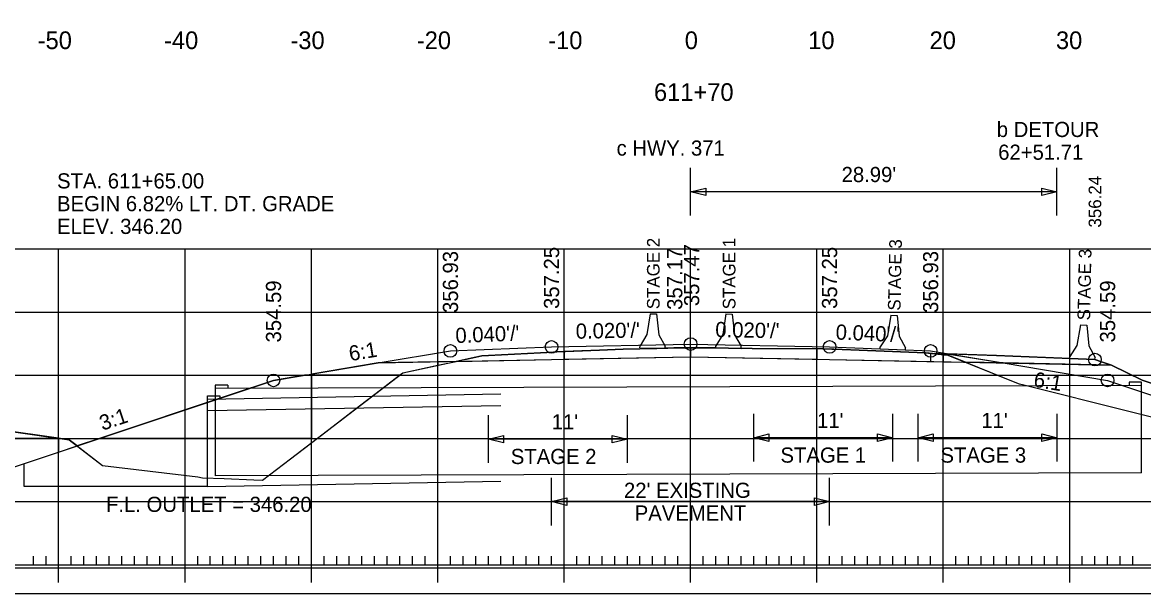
# Model space of a CAD drawing. Extents: x 1368910 to 1369601, y 380116 to 380950.
# Drawn here: x 1369384.7 to 1369473.4, y 380417.2 to 380462.3 of the extents above; entities that cross this region are included whole.
import ezdxf

# ---------------------------------------------------------------- set-up
doc = ezdxf.new("R2010")
doc.units = 0
for name, color, linetype in [('_STAGE 1 CUT', 7, 'Continuous'), ('_STAGE 1 FILL', 7, 'Continuous'), ('_STAGE 2 CUT', 7, 'Continuous'), ('_STAGE 2 FILL', 7, 'Continuous'), ('_STAGE 4 CUT', 7, 'Continuous'), ('Notes', 7, 'Continuous'), ('R_Alt Surface', 7, 'Continuous'), ('R_Axis', 7, 'Continuous'), ('R_Axis Annot', 7, 'Continuous'), ('R_Border Plan-Plan', 7, 'Continuous'), ('R_CONC BARRIER', 7, 'Continuous'), ('R_Detour', 7, 'Continuous'), ('R_Detour Surface', 7, 'Continuous'), ('R_Exist Surface', 7, 'Continuous'), ('R_Fin Surface', 7, 'Continuous'), ('R_Grid', 7, 'Continuous'), ('R_No Plot', 7, 'Continuous'), ('R_ROW Annot', 7, 'Continuous'), ('R_Water', 7, 'Continuous'), ('R_Xsect Elev', 7, 'Continuous'), ('R_Xsect Elev Detour', 7, 'Continuous'), ('R_Xsect Slope', 7, 'Continuous')]:
    doc.layers.add(name, color=color, linetype=linetype)

msp = doc.modelspace()

# ---------------------------------------------------------------- linework, layer by layer
at = {"layer": '_STAGE 1 CUT'}
for p, q in [((1369437.59, 380435.886), (1369437.59, 380436.594)), ((1369419.052, 380435.516), (1369426.59, 380435.666)), ((1369426.59, 380435.666), (1369427.59, 380435.686)), ((1369427.59, 380435.686), (1369427.59, 380436.292)), ((1369427.59, 380436.292), (1369427.59, 380435.686)), ((1369427.59, 380435.686), (1369437.59, 380435.886)), ((1369387.59, 380429.441), (1369378.835, 380430.689)), ((1369387.59, 380429.421), (1369377.59, 380429.421)), ((1369377.59, 380429.421), (1369387.59, 380429.421)), ((1369387.59, 380429.421), (1369387.59, 380429.441)), ((1369387.59, 380428.346), (1369387.59, 380429.421)), ((1369387.732, 380429.421), (1369387.59, 380429.421)), ((1369387.59, 380429.421), (1369387.59, 380428.346)), ((1369387.59, 380428.346), (1369389.057, 380428.836)), ((1369379.419, 380425.623), (1369387.59, 380428.346))]:
    msp.add_line(p, q, dxfattribs=at)
for points in [[(1369437.59, 380436.594), (1369437.463, 380436.593), (1369437.33, 380436.595), (1369436.264, 380436.589), (1369435.797, 380436.559), (1369435.59, 380436.553), (1369434.929, 380436.533), (1369432.263, 380436.481), (1369430.399, 380436.402), (1369427.59, 380436.292)], [(1369427.59, 380436.292), (1369427.004, 380436.269), (1369426.753, 380436.249), (1369421.601, 380435.996), (1369421.087, 380435.969), (1369420.613, 380435.845), (1369419.052, 380435.516)], [(1369389.057, 380428.836), (1369388.429, 380429.321), (1369387.732, 380429.421)]]:
    msp.add_lwpolyline(points, dxfattribs=at)
at = {"layer": '_STAGE 1 FILL'}
for p, q in [((1369417.59, 380435.208), (1369419.052, 380435.516)), ((1369419.052, 380435.516), (1369417.59, 380435.486)), ((1369412.863, 380435.392), (1369407.59, 380434.513)), ((1369417.59, 380435.486), (1369412.863, 380435.392)), ((1369417.59, 380435.486), (1369417.59, 380435.208)), ((1369417.59, 380435.208), (1369417.59, 380435.486)), ((1369407.036, 380434.421), (1369404.59, 380434.013)), ((1369407.59, 380434.421), (1369407.036, 380434.421)), ((1369407.59, 380434.513), (1369407.59, 380434.421)), ((1369407.59, 380434.421), (1369414.554, 380434.421)), ((1369414.554, 380434.421), (1369407.59, 380434.421)), ((1369407.59, 380434.421), (1369407.59, 380432.947)), ((1369407.59, 380432.947), (1369407.59, 380434.421)), ((1369390.813, 380429.421), (1369389.057, 380428.836)), ((1369390.813, 380429.421), (1369407.59, 380429.421)), ((1369407.59, 380429.421), (1369390.813, 380429.421)), ((1369407.59, 380429.421), (1369408.032, 380429.421)), ((1369407.59, 380429.082), (1369407.59, 380429.421))]:
    msp.add_line(p, q, dxfattribs=at)
for points in [[(1369414.554, 380434.421), (1369414.819, 380434.624), (1369417.59, 380435.208)], [(1369404.59, 380434.013), (1369401.171, 380432.873), (1369390.813, 380429.421)], [(1369408.032, 380429.421), (1369411.384, 380431.991), (1369412.708, 380433.006), (1369414.554, 380434.421)], [(1369407.59, 380432.947), (1369407.59, 380431.947), (1369407.59, 380429.421)], [(1369407.59, 380429.421), (1369407.59, 380431.947), (1369407.59, 380432.947)], [(1369389.057, 380428.836), (1369391.051, 380427.292), (1369398.609, 380426.388), (1369398.964, 380426.295), (1369400.673, 380426.251), (1369403.029, 380426.16), (1369403.724, 380426.13), (1369405.923, 380427.804), (1369407.59, 380429.082)]]:
    msp.add_lwpolyline(points, dxfattribs=at)
at = {"layer": '_STAGE 2 CUT'}
for p, q in [((1369437.59, 380436.594), (1369437.59, 380435.886)), ((1369441.59, 380436.548), (1369439.59, 380436.588)), ((1369441.59, 380436.556), (1369441.59, 380436.548)), ((1369447.59, 380436.519), (1369447.59, 380435.686)), ((1369447.59, 380435.686), (1369447.59, 380436.519)), ((1369437.59, 380435.886), (1369447.59, 380435.686)), ((1369447.59, 380435.686), (1369448.59, 380435.666)), ((1369448.59, 380435.666), (1369457.59, 380435.486)), ((1369457.59, 380435.486), (1369457.59, 380436.053)), ((1369457.59, 380436.053), (1369457.59, 380435.486)), ((1369457.59, 380435.486), (1369459.349, 380435.451))]:
    msp.add_line(p, q, dxfattribs=at)
for points in [[(1369439.59, 380436.588), (1369438.794, 380436.601), (1369437.59, 380436.594)], [(1369447.59, 380436.519), (1369442.479, 380436.542), (1369441.59, 380436.556)], [(1369457.59, 380436.053), (1369456.193, 380436.192), (1369451.59, 380436.381), (1369448.928, 380436.485), (1369448.773, 380436.49), (1369448.065, 380436.517), (1369447.59, 380436.519)], [(1369459.349, 380435.451), (1369457.951, 380436.013), (1369457.653, 380436.046), (1369457.59, 380436.053)]]:
    msp.add_lwpolyline(points, dxfattribs=at)
at = {"layer": '_STAGE 2 FILL'}
for p, q in [((1369462.317, 380435.392), (1369459.349, 380435.451)), ((1369470.909, 380435.22), (1369462.317, 380435.392))]:
    msp.add_line(p, q, dxfattribs=at)
for points in [[(1369459.349, 380435.451), (1369463.243, 380433.885), (1369463.583, 380433.733), (1369463.856, 380433.68), (1369481.105, 380429.375), (1369481.631, 380429.201), (1369481.702, 380429.203), (1369484.652, 380429.137), (1369485.064, 380429.188), (1369486.052, 380429.311)], [(1369462.317, 380435.392), (1369462.317, 380435.392)], [(1369487.523, 380429.468), (1369485.977, 380429.824), (1369473.317, 380434.045), (1369470.909, 380435.22)]]:
    msp.add_lwpolyline(points, dxfattribs=at)
at = {"layer": '_STAGE 4 CUT'}
for p, q in [((1369457.904, 380436.127), (1369462.315, 380435.392)), ((1369462.315, 380435.392), (1369462.317, 380435.392))]:
    msp.add_line(p, q, dxfattribs=at)
for points in [[(1369470.118, 380435.484), (1369469.59, 380435.66), (1369467.592, 380435.74), (1369461.79, 380435.972), (1369457.904, 380436.127)], [(1369462.317, 380435.392), (1369462.317, 380435.392)], [(1369462.317, 380435.392), (1369470.59, 380434.013), (1369485.064, 380429.188), (1369485.665, 380428.988), (1369489.605, 380428.988)], [(1369489.605, 380428.988), (1369487.523, 380429.468), (1369485.977, 380429.824), (1369473.317, 380434.045), (1369470.909, 380435.22), (1369470.118, 380435.484)]]:
    msp.add_lwpolyline(points, dxfattribs=at)
at = {"layer": 'R_Alt Surface'}
for points in [[(1369412.863, 380435.392), (1369426.59, 380435.666), (1369437.59, 380435.886), (1369448.59, 380435.666), (1369462.317, 380435.392)], [(1369456.59, 380436.18), (1369456.59, 380435.507), (1369470.909, 380435.22)]]:
    msp.add_lwpolyline(points, dxfattribs=at)
at = {"layer": 'R_Axis'}
for p, q in [((1369387.59, 380418.021), (1369387.59, 380420.821)), ((1369397.59, 380418.021), (1369397.59, 380420.821)), ((1369407.59, 380418.021), (1369407.59, 380420.821)), ((1369417.59, 380418.021), (1369417.59, 380420.821)), ((1369427.59, 380418.021), (1369427.59, 380420.821)), ((1369437.59, 380418.021), (1369437.59, 380420.821)), ((1369447.59, 380418.021), (1369447.59, 380420.821)), ((1369457.59, 380418.021), (1369457.59, 380420.821)), ((1369467.59, 380418.021), (1369467.59, 380420.821)), ((1369385.59, 380419.421), (1369385.59, 380420.121)), ((1369386.59, 380419.421), (1369386.59, 380420.121)), ((1369388.59, 380419.421), (1369388.59, 380420.121)), ((1369389.59, 380419.421), (1369389.59, 380420.121)), ((1369390.59, 380419.421), (1369390.59, 380420.121)), ((1369391.59, 380419.421), (1369391.59, 380420.121)), ((1369392.59, 380419.421), (1369392.59, 380420.121)), ((1369393.59, 380419.421), (1369393.59, 380420.121)), ((1369394.59, 380419.421), (1369394.59, 380420.121)), ((1369395.59, 380419.421), (1369395.59, 380420.121)), ((1369396.59, 380419.421), (1369396.59, 380420.121)), ((1369398.59, 380419.421), (1369398.59, 380420.121)), ((1369399.59, 380419.421), (1369399.59, 380420.121)), ((1369400.59, 380419.421), (1369400.59, 380420.121)), ((1369401.59, 380419.421), (1369401.59, 380420.121)), ((1369402.59, 380419.421), (1369402.59, 380420.121)), ((1369403.59, 380419.421), (1369403.59, 380420.121)), ((1369404.59, 380419.421), (1369404.59, 380420.121)), ((1369405.59, 380419.421), (1369405.59, 380420.121)), ((1369406.59, 380419.421), (1369406.59, 380420.121)), ((1369408.59, 380419.421), (1369408.59, 380420.121)), ((1369409.59, 380419.421), (1369409.59, 380420.121)), ((1369410.59, 380419.421), (1369410.59, 380420.121)), ((1369411.59, 380419.421), (1369411.59, 380420.121)), ((1369412.59, 380419.421), (1369412.59, 380420.121)), ((1369413.59, 380419.421), (1369413.59, 380420.121)), ((1369414.59, 380419.421), (1369414.59, 380420.121)), ((1369415.59, 380419.421), (1369415.59, 380420.121)), ((1369416.59, 380419.421), (1369416.59, 380420.121)), ((1369418.59, 380419.421), (1369418.59, 380420.121)), ((1369419.59, 380419.421), (1369419.59, 380420.121)), ((1369420.59, 380419.421), (1369420.59, 380420.121)), ((1369421.59, 380419.421), (1369421.59, 380420.121)), ((1369422.59, 380419.421), (1369422.59, 380420.121)), ((1369423.59, 380419.421), (1369423.59, 380420.121)), ((1369424.59, 380419.421), (1369424.59, 380420.121)), ((1369425.59, 380419.421), (1369425.59, 380420.121)), ((1369426.59, 380419.421), (1369426.59, 380420.121)), ((1369428.59, 380419.421), (1369428.59, 380420.121)), ((1369429.59, 380419.421), (1369429.59, 380420.121)), ((1369430.59, 380419.421), (1369430.59, 380420.121)), ((1369431.59, 380419.421), (1369431.59, 380420.121)), ((1369432.59, 380419.421), (1369432.59, 380420.121)), ((1369433.59, 380419.421), (1369433.59, 380420.121)), ((1369434.59, 380419.421), (1369434.59, 380420.121)), ((1369435.59, 380419.421), (1369435.59, 380420.121)), ((1369436.59, 380419.421), (1369436.59, 380420.121)), ((1369438.59, 380419.421), (1369438.59, 380420.121)), ((1369439.59, 380419.421), (1369439.59, 380420.121)), ((1369440.59, 380419.421), (1369440.59, 380420.121)), ((1369441.59, 380419.421), (1369441.59, 380420.121)), ((1369442.59, 380419.421), (1369442.59, 380420.121)), ((1369443.59, 380419.421), (1369443.59, 380420.121)), ((1369444.59, 380419.421), (1369444.59, 380420.121)), ((1369445.59, 380419.421), (1369445.59, 380420.121)), ((1369446.59, 380419.421), (1369446.59, 380420.121)), ((1369448.59, 380419.421), (1369448.59, 380420.121)), ((1369449.59, 380419.421), (1369449.59, 380420.121)), ((1369450.59, 380419.421), (1369450.59, 380420.121)), ((1369451.59, 380419.421), (1369451.59, 380420.121)), ((1369452.59, 380419.421), (1369452.59, 380420.121)), ((1369453.59, 380419.421), (1369453.59, 380420.121)), ((1369454.59, 380419.421), (1369454.59, 380420.121)), ((1369455.59, 380419.421), (1369455.59, 380420.121)), ((1369456.59, 380419.421), (1369456.59, 380420.121)), ((1369458.59, 380419.421), (1369458.59, 380420.121)), ((1369459.59, 380419.421), (1369459.59, 380420.121)), ((1369460.59, 380419.421), (1369460.59, 380420.121)), ((1369461.59, 380419.421), (1369461.59, 380420.121)), ((1369462.59, 380419.421), (1369462.59, 380420.121)), ((1369463.59, 380419.421), (1369463.59, 380420.121)), ((1369464.59, 380419.421), (1369464.59, 380420.121)), ((1369465.59, 380419.421), (1369465.59, 380420.121)), ((1369466.59, 380419.421), (1369466.59, 380420.121)), ((1369468.59, 380419.421), (1369468.59, 380420.121)), ((1369469.59, 380419.421), (1369469.59, 380420.121)), ((1369470.59, 380419.421), (1369470.59, 380420.121)), ((1369471.59, 380419.421), (1369471.59, 380420.121)), ((1369472.59, 380419.421), (1369472.59, 380420.121)), ((1369297.59, 380419.421), (1369577.59, 380419.421))]:
    msp.add_line(p, q, dxfattribs=at)
at = {"layer": 'R_Border Plan-Plan'}
msp.add_line((1369279.59, 380417.151), (1369595.77, 380417.151), dxfattribs=at)
at = {"layer": 'R_CONC BARRIER'}
for p, q in [((1369434.394, 380439.277), (1369434.894, 380439.267)), ((1369440.394, 380439.272), (1369440.894, 380439.262)), ((1369453.447, 380439.175), (1369453.947, 380439.155)), ((1369468.449, 380438.408), (1369468.948, 380438.388)), ((1369433.59, 380436.593), (1369433.594, 380436.759)), ((1369433.59, 380436.593), (1369435.59, 380436.553)), ((1369435.59, 380436.553), (1369435.593, 380436.719)), ((1369439.59, 380436.588), (1369439.593, 380436.755)), ((1369439.59, 380436.588), (1369441.59, 380436.548)), ((1369441.59, 380436.548), (1369441.593, 380436.715)), ((1369452.59, 380436.507), (1369452.597, 380436.673)), ((1369452.59, 380436.507), (1369454.588, 380436.427)), ((1369454.588, 380436.427), (1369454.595, 380436.593)), ((1369467.592, 380435.74), (1369467.598, 380435.907)), ((1369467.592, 380435.74), (1369469.59, 380435.66)), ((1369469.59, 380435.66), (1369469.597, 380435.827))]:
    msp.add_line(p, q, dxfattribs=at)
for points in [[(1369434.394, 380439.277), (1369434.143, 380437.639), (1369433.594, 380436.759)], [(1369434.894, 380439.267), (1369435.08, 380437.62), (1369435.593, 380436.719)], [(1369440.394, 380439.272), (1369440.142, 380437.634), (1369439.593, 380436.755)], [(1369440.894, 380439.262), (1369441.079, 380437.616), (1369441.593, 380436.715)], [(1369453.447, 380439.175), (1369453.163, 380437.542), (1369452.597, 380436.673)], [(1369453.947, 380439.155), (1369454.1, 380437.504), (1369454.595, 380436.593)], [(1369468.449, 380438.408), (1369468.165, 380436.775), (1369467.598, 380435.907)], [(1369468.948, 380438.388), (1369469.101, 380436.738), (1369469.597, 380435.827)]]:
    msp.add_lwpolyline(points, dxfattribs=at)
at = {"layer": 'R_Detour'}
for p, q in [((1369473.286, 380433.866), (1369472.286, 380433.866)), ((1369472.286, 380433.866), (1369472.286, 380433.613)), ((1369473.286, 380433.616), (1369473.286, 380433.866)), ((1369400.983, 380433.631), (1369399.983, 380433.631)), ((1369399.983, 380433.631), (1369399.983, 380433.378)), ((1369473.286, 380433.616), (1369399.983, 380433.378)), ((1369399.983, 380433.378), (1369399.983, 380426.461)), ((1369400.983, 380433.631), (1369400.983, 380433.378)), ((1369473.286, 380432.699), (1369473.286, 380433.616)), ((1369473.286, 380426.699), (1369473.286, 380432.699)), ((1369473.286, 380426.699), (1369399.983, 380426.461))]:
    msp.add_line(p, q, dxfattribs=at)
at = {"layer": 'R_Detour Surface'}
msp.add_lwpolyline([(1369456.59, 380436.18), (1369461.79, 380435.972), (1369469.59, 380435.66), (1369470.118, 380435.484), (1369470.909, 380435.22), (1369473.317, 380434.045), (1369485.977, 380429.824), (1369489.605, 380428.988)], dxfattribs=at)
at = {"layer": 'R_Exist Surface'}
msp.add_lwpolyline([(1369378.835, 380430.689), (1369388.429, 380429.321), (1369391.051, 380427.292), (1369398.609, 380426.388), (1369398.964, 380426.295), (1369400.673, 380426.251), (1369403.029, 380426.16), (1369403.724, 380426.13), (1369405.923, 380427.804), (1369414.819, 380434.624), (1369420.613, 380435.845), (1369421.087, 380435.969), (1369421.601, 380435.996), (1369426.753, 380436.249), (1369427.004, 380436.269), (1369430.399, 380436.402), (1369432.263, 380436.481), (1369434.929, 380436.533), (1369435.797, 380436.559), (1369436.264, 380436.589), (1369437.33, 380436.595), (1369437.463, 380436.593), (1369438.794, 380436.601), (1369442.479, 380436.542), (1369448.065, 380436.517), (1369448.773, 380436.49), (1369448.928, 380436.485), (1369451.59, 380436.381), (1369456.193, 380436.192), (1369457.653, 380436.046), (1369457.951, 380436.013), (1369463.243, 380433.885), (1369463.583, 380433.733), (1369463.856, 380433.68), (1369481.105, 380429.375)], dxfattribs=at)
at = {"layer": 'R_Fin Surface'}
msp.add_lwpolyline([(1369354.292, 380430.661), (1369369.413, 380425.621), (1369379.413, 380425.621), (1369404.59, 380434.013), (1369412.863, 380435.392), (1369418.59, 380436.346), (1369426.59, 380436.666), (1369437.59, 380436.886), (1369448.59, 380436.666), (1369456.59, 380436.346), (1369462.317, 380435.392), (1369470.59, 380434.013), (1369485.665, 380428.988), (1369490.579, 380428.988), (1369494.234, 380430.207)], dxfattribs=at)
at = {"layer": 'R_Grid'}
for p, q in [((1369297.59, 380444.421), (1369577.59, 380444.421)), ((1369297.59, 380444.421), (1369577.59, 380444.421)), ((1369387.59, 380419.421), (1369387.59, 380444.421)), ((1369387.59, 380419.421), (1369387.59, 380444.421)), ((1369397.59, 380419.421), (1369397.59, 380444.421)), ((1369397.59, 380419.421), (1369397.59, 380444.421)), ((1369407.59, 380419.421), (1369407.59, 380444.421)), ((1369407.59, 380419.421), (1369407.59, 380444.421)), ((1369417.59, 380419.421), (1369417.59, 380444.421)), ((1369417.59, 380419.421), (1369417.59, 380444.421)), ((1369427.59, 380419.421), (1369427.59, 380444.421)), ((1369427.59, 380419.421), (1369427.59, 380444.421)), ((1369437.59, 380419.421), (1369437.59, 380444.421)), ((1369437.59, 380419.421), (1369437.59, 380444.421)), ((1369447.59, 380419.421), (1369447.59, 380444.421)), ((1369447.59, 380419.421), (1369447.59, 380444.421)), ((1369457.59, 380419.421), (1369457.59, 380444.421)), ((1369457.59, 380419.421), (1369457.59, 380444.421)), ((1369467.59, 380419.421), (1369467.59, 380444.421)), ((1369467.59, 380419.421), (1369467.59, 380444.421)), ((1369297.59, 380439.421), (1369577.59, 380439.421)), ((1369297.59, 380439.421), (1369577.59, 380439.421)), ((1369297.59, 380434.421), (1369577.59, 380434.421)), ((1369297.59, 380434.421), (1369577.59, 380434.421)), ((1369297.59, 380429.421), (1369577.59, 380429.421)), ((1369297.59, 380429.421), (1369577.59, 380429.421)), ((1369297.59, 380424.421), (1369577.59, 380424.421)), ((1369297.59, 380424.421), (1369577.59, 380424.421)), ((1369297.59, 380419.421), (1369577.59, 380419.421)), ((1369297.59, 380419.421), (1369577.59, 380419.421))]:
    msp.add_line(p, q, dxfattribs=at)
at = {"layer": 'R_No Plot'}
msp.add_lwpolyline([(1369593.77, 380419.151), (1369281.59, 380419.151), (1369281.59, 380517.881), (1369531.13, 380517.881), (1369531.13, 380508.001), (1369548.67, 380508.001), (1369572.77, 380508.001), (1369572.77, 380485.668), (1369593.77, 380485.668)], close=True, dxfattribs=at)
for centre in [(1369437.59, 380436.886), (1369418.59, 380436.346), (1369426.59, 380436.666), (1369448.59, 380436.666), (1369456.59, 380436.346), (1369469.59, 380435.66), (1369404.59, 380434.013), (1369470.59, 380434.013)]:
    msp.add_circle(centre, 0.5, dxfattribs=at)
at = {"layer": 'R_ROW Annot'}
for p, q in [((1369437.59, 380447.047), (1369437.59, 380450.816)), ((1369466.58, 380447.047), (1369466.58, 380450.816)), ((1369466.58, 380448.932), (1369437.59, 380448.932)), ((1369421.59, 380427.482), (1369421.59, 380431.251)), ((1369432.59, 380427.482), (1369432.59, 380431.251)), ((1369442.59, 380427.592), (1369442.59, 380431.36)), ((1369453.59, 380427.592), (1369453.59, 380431.36)), ((1369455.59, 380427.592), (1369455.59, 380431.36)), ((1369466.59, 380427.592), (1369466.59, 380431.36)), ((1369432.59, 380429.366), (1369421.59, 380429.366)), ((1369453.59, 380429.476), (1369442.59, 380429.476)), ((1369466.59, 380429.476), (1369455.59, 380429.476)), ((1369426.59, 380422.537), (1369426.59, 380426.305)), ((1369448.59, 380422.537), (1369448.59, 380426.305)), ((1369448.59, 380424.421), (1369426.59, 380424.421))]:
    msp.add_line(p, q, dxfattribs=at)
for points in [[(1369438.79, 380448.632), (1369437.59, 380448.932), (1369438.79, 380449.232)], [(1369465.38, 380449.232), (1369466.58, 380448.932), (1369465.38, 380448.632)], [(1369422.79, 380429.066), (1369421.59, 380429.366), (1369422.79, 380429.666)], [(1369431.39, 380429.666), (1369432.59, 380429.366), (1369431.39, 380429.066)], [(1369443.79, 380429.176), (1369442.59, 380429.476), (1369443.79, 380429.776)], [(1369452.39, 380429.776), (1369453.59, 380429.476), (1369452.39, 380429.176)], [(1369456.79, 380429.176), (1369455.59, 380429.476), (1369456.79, 380429.776)], [(1369465.39, 380429.776), (1369466.59, 380429.476), (1369465.39, 380429.176)], [(1369427.79, 380424.121), (1369426.59, 380424.421), (1369427.79, 380424.721)], [(1369447.39, 380424.721), (1369448.59, 380424.421), (1369447.39, 380424.121)]]:
    msp.add_lwpolyline(points, close=True, dxfattribs=at)
at = {"layer": 'R_Water'}
for p, q in [((1369399.355, 380432.537), (1369422.59, 380432.948)), ((1369399.355, 380431.621), (1369422.59, 380432.031)), ((1369399.355, 380425.621), (1369422.59, 380426.031))]:
    msp.add_line(p, q, dxfattribs=at)
for points in [[(1369399.355, 380425.621), (1369399.355, 380431.621), (1369399.355, 380432.537), (1369399.355, 380432.787), (1369400.355, 380432.787), (1369400.355, 380432.537)], [(1369399.355, 380425.621), (1369384.855, 380425.621), (1369384.855, 380427.435)]]:
    msp.add_lwpolyline(points, dxfattribs=at)

# ---------------------------------------------------------------- texts
at = {"layer": 'Notes'}
for s, p in [('b DETOUR', (1369461.821, 380453.266)), ('c HWY. 371', (1369431.74, 380451.793)), ('62+51.71', (1369461.933, 380451.466)), ('STA. 611+65.00', (1369387.463, 380449.197)), ('BEGIN 6.82% LT. DT. GRADE', (1369387.463, 380447.397)), ('ELEV. 346.20', (1369387.463, 380445.597))]:
    msp.add_text(s, height=1.2, dxfattribs=at).set_placement(p)
at = {"layer": 'R_Axis Annot'}
for s, p in [('-50', (1369385.931, 380460.221)), ('-40', (1369395.931, 380460.221)), ('-30', (1369405.931, 380460.221)), ('-20', (1369415.931, 380460.221)), ('-10', (1369426.328, 380460.221)), ('0', (1369437.132, 380460.221)), ('10', (1369446.901, 380460.221)), ('20', (1369456.504, 380460.221)), ('30', (1369466.504, 380460.221)), ('611+70', (1369434.696, 380456.121))]:
    msp.add_text(s, height=1.4, dxfattribs=at).set_placement(p)
at = {"layer": 'R_CONC BARRIER'}
for s, rotation, p in [(' STAGE 2', 90, (1369435.144, 380439.272)), (' STAGE 1', 90, (1369441.144, 380439.267)), (' STAGE 3', 88.85515, (1369454.197, 380439.155)), (' STAGE 3', 88.85515, (1369469.199, 380438.388))]:
    msp.add_text(s, height=1, rotation=rotation, dxfattribs=at).set_placement(p)
at = {"layer": 'R_ROW Annot'}
for s, p in [("28.99'", (1369449.543, 380449.701)), ("11'", (1369426.599, 380430.136)), ("11'", (1369447.599, 380430.246)), ("11'", (1369460.599, 380430.246)), ('STAGE 2', (1369423.367, 380427.397)), ('STAGE 1', (1369444.707, 380427.506)), ('STAGE 3', (1369457.367, 380427.506)), ("22' EXISTING", (1369432.322, 380424.721)), ('PAVEMENT', (1369433.173, 380422.921))]:
    msp.add_text(s, height=1.2, dxfattribs=at).set_placement(p)
at = {"layer": 'R_Xsect Elev'}
for s, p in [('357.25', (1369427.19, 380439.666)), ('357.17', (1369436.94, 380439.594)), ('357.47', (1369438.277, 380439.886)), ('357.25', (1369449.19, 380439.666)), ('356.93', (1369419.19, 380439.346)), ('356.93', (1369457.19, 380439.346)), ('354.59', (1369405.19, 380437.013)), ('354.59', (1369471.19, 380437.013))]:
    msp.add_text(s, height=1.2, rotation=90, dxfattribs=at).set_placement(p)
at = {"layer": 'R_Xsect Elev Detour'}
msp.add_text('356.24', height=1, rotation=90, dxfattribs=at).set_placement((1369470.09, 380446.103))
at = {"layer": 'R_Xsect Slope'}
for s, rotation, p in [("0.040'/'", 2.29061, (1369419.007, 380436.964)), ("0.020'/'", 1.14576, (1369428.516, 380437.305)), ("0.020'/'", 358.85424, (1369439.54, 380437.448)), ("0.040'/'", 357.70939, (1369449.055, 380437.248)), ('6:1', 9.46234, (1369410.66, 380435.532)), ('6:1', 350.53766, (1369464.679, 380433.526)), ('3:1', 18.43493, (1369391.055, 380430.028)), ('F.L. OUTLET = 346.20', 360, (1369391.335, 380423.609))]:
    msp.add_text(s, height=1.2, rotation=rotation, dxfattribs=at).set_placement(p)

doc.saveas('drawing.dxf')
